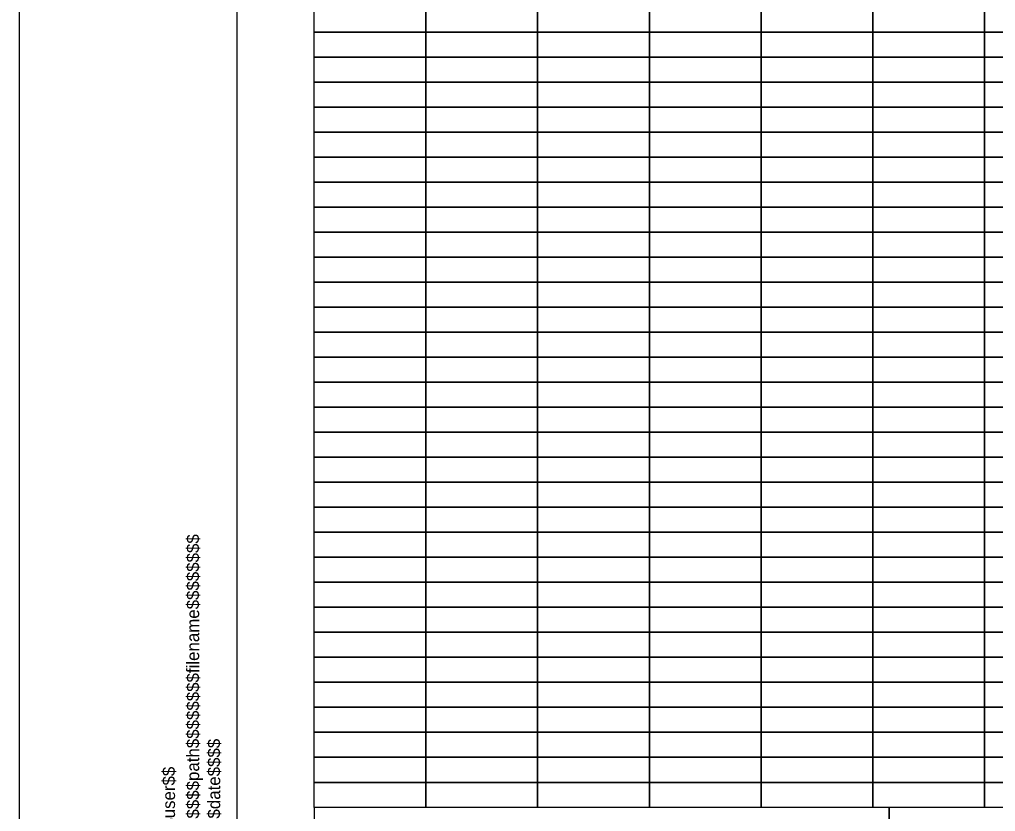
# Model space of a CAD drawing. Extents: x 14330 to 16126, y 15844 to 16994.
# Drawn here: x 14329.7 to 14784.3, y 16045.6 to 16414.6 of the extents above; entities that cross this region are included whole.
import ezdxf

# ---------------------------------------------------------------- set-up
doc = ezdxf.new("R2010")
doc.units = 0
for name, color, linetype in [('RD_SHT_Bndy', 7, 'Continuous'), ('RD_SHT_ID', 7, 'Continuous'), ('RD_SHT_Iplotshp', 7, 'Continuous'), ('RD_SHT_Snap', 7, 'Continuous')]:
    doc.layers.add(name, color=color, linetype=linetype)

msp = doc.modelspace()

# ---------------------------------------------------------------- linework, layer by layer
at = {"layer": 'RD_SHT_Bndy'}
msp.add_line((14430.85, 16943.63), (14430.85, 15893.63), dxfattribs=at)
for points in [[(14518.98, 16408.81), (14466.94, 16408.81), (14466.94, 16420.46), (14518.98, 16420.46)], [(14571.02, 16408.81), (14518.98, 16408.81), (14518.98, 16420.46), (14571.02, 16420.46)], [(14623.07, 16408.81), (14571.02, 16408.81), (14571.02, 16420.46), (14623.07, 16420.46)], [(14675.11, 16408.81), (14623.07, 16408.81), (14623.07, 16420.46), (14675.11, 16420.46)], [(14727.15, 16408.81), (14675.11, 16408.81), (14675.11, 16420.46), (14727.15, 16420.46)], [(14779.19, 16408.81), (14727.15, 16408.81), (14727.15, 16420.46), (14779.19, 16420.46)], [(14831.23, 16408.81), (14779.19, 16408.81), (14779.19, 16420.46), (14831.23, 16420.46)], [(14518.98, 16397.15), (14466.94, 16397.15), (14466.94, 16408.81), (14518.98, 16408.81)], [(14571.02, 16397.15), (14518.98, 16397.15), (14518.98, 16408.81), (14571.02, 16408.81)], [(14623.07, 16397.15), (14571.02, 16397.15), (14571.02, 16408.81), (14623.07, 16408.81)], [(14675.11, 16397.15), (14623.07, 16397.15), (14623.07, 16408.81), (14675.11, 16408.81)], [(14727.15, 16397.15), (14675.11, 16397.15), (14675.11, 16408.81), (14727.15, 16408.81)], [(14779.19, 16397.15), (14727.15, 16397.15), (14727.15, 16408.81), (14779.19, 16408.81)], [(14831.23, 16397.15), (14779.19, 16397.15), (14779.19, 16408.81), (14831.23, 16408.81)], [(14518.98, 16385.5), (14466.94, 16385.5), (14466.94, 16397.15), (14518.98, 16397.15)], [(14571.02, 16385.5), (14518.98, 16385.5), (14518.98, 16397.15), (14571.02, 16397.15)], [(14623.07, 16385.5), (14571.02, 16385.5), (14571.02, 16397.15), (14623.07, 16397.15)], [(14675.11, 16385.5), (14623.07, 16385.5), (14623.07, 16397.15), (14675.11, 16397.15)], [(14727.15, 16385.5), (14675.11, 16385.5), (14675.11, 16397.15), (14727.15, 16397.15)], [(14779.19, 16385.5), (14727.15, 16385.5), (14727.15, 16397.15), (14779.19, 16397.15)], [(14831.23, 16385.5), (14779.19, 16385.5), (14779.19, 16397.15), (14831.23, 16397.15)], [(14518.98, 16373.84), (14466.94, 16373.84), (14466.94, 16385.5), (14518.98, 16385.5)], [(14571.02, 16373.84), (14518.98, 16373.84), (14518.98, 16385.5), (14571.02, 16385.5)], [(14623.07, 16373.84), (14571.02, 16373.84), (14571.02, 16385.5), (14623.07, 16385.5)], [(14675.11, 16373.84), (14623.07, 16373.84), (14623.07, 16385.5), (14675.11, 16385.5)], [(14727.15, 16373.84), (14675.11, 16373.84), (14675.11, 16385.5), (14727.15, 16385.5)], [(14779.19, 16373.84), (14727.15, 16373.84), (14727.15, 16385.5), (14779.19, 16385.5)], [(14831.23, 16373.84), (14779.19, 16373.84), (14779.19, 16385.5), (14831.23, 16385.5)], [(14518.98, 16362.19), (14466.94, 16362.19), (14466.94, 16373.84), (14518.98, 16373.84)], [(14571.02, 16362.19), (14518.98, 16362.19), (14518.98, 16373.84), (14571.02, 16373.84)], [(14623.07, 16362.19), (14571.02, 16362.19), (14571.02, 16373.84), (14623.07, 16373.84)], [(14675.11, 16362.19), (14623.07, 16362.19), (14623.07, 16373.84), (14675.11, 16373.84)], [(14727.15, 16362.19), (14675.11, 16362.19), (14675.11, 16373.84), (14727.15, 16373.84)], [(14779.19, 16362.19), (14727.15, 16362.19), (14727.15, 16373.84), (14779.19, 16373.84)], [(14831.23, 16362.19), (14779.19, 16362.19), (14779.19, 16373.84), (14831.23, 16373.84)], [(14518.98, 16350.53), (14466.94, 16350.53), (14466.94, 16362.19), (14518.98, 16362.19)], [(14571.02, 16350.53), (14518.98, 16350.53), (14518.98, 16362.19), (14571.02, 16362.19)], [(14623.07, 16350.53), (14571.02, 16350.53), (14571.02, 16362.19), (14623.07, 16362.19)], [(14675.11, 16350.53), (14623.07, 16350.53), (14623.07, 16362.19), (14675.11, 16362.19)], [(14727.15, 16350.53), (14675.11, 16350.53), (14675.11, 16362.19), (14727.15, 16362.19)], [(14779.19, 16350.53), (14727.15, 16350.53), (14727.15, 16362.19), (14779.19, 16362.19)], [(14831.23, 16350.53), (14779.19, 16350.53), (14779.19, 16362.19), (14831.23, 16362.19)], [(14518.98, 16338.88), (14466.94, 16338.88), (14466.94, 16350.53), (14518.98, 16350.53)], [(14571.02, 16338.88), (14518.98, 16338.88), (14518.98, 16350.53), (14571.02, 16350.53)], [(14623.07, 16338.88), (14571.02, 16338.88), (14571.02, 16350.53), (14623.07, 16350.53)], [(14675.11, 16338.88), (14623.07, 16338.88), (14623.07, 16350.53), (14675.11, 16350.53)], [(14727.15, 16338.88), (14675.11, 16338.88), (14675.11, 16350.53), (14727.15, 16350.53)], [(14779.19, 16338.88), (14727.15, 16338.88), (14727.15, 16350.53), (14779.19, 16350.53)], [(14831.23, 16338.88), (14779.19, 16338.88), (14779.19, 16350.53), (14831.23, 16350.53)], [(14518.98, 16327.22), (14466.94, 16327.22), (14466.94, 16338.88), (14518.98, 16338.88)], [(14571.02, 16327.22), (14518.98, 16327.22), (14518.98, 16338.88), (14571.02, 16338.88)], [(14623.07, 16327.22), (14571.02, 16327.22), (14571.02, 16338.88), (14623.07, 16338.88)], [(14675.11, 16327.22), (14623.07, 16327.22), (14623.07, 16338.88), (14675.11, 16338.88)], [(14727.15, 16327.22), (14675.11, 16327.22), (14675.11, 16338.88), (14727.15, 16338.88)], [(14779.19, 16327.22), (14727.15, 16327.22), (14727.15, 16338.88), (14779.19, 16338.88)], [(14831.23, 16327.22), (14779.19, 16327.22), (14779.19, 16338.88), (14831.23, 16338.88)], [(14518.98, 16315.57), (14466.94, 16315.57), (14466.94, 16327.22), (14518.98, 16327.22)], [(14571.02, 16315.57), (14518.98, 16315.57), (14518.98, 16327.22), (14571.02, 16327.22)], [(14623.07, 16315.57), (14571.02, 16315.57), (14571.02, 16327.22), (14623.07, 16327.22)], [(14675.11, 16315.57), (14623.07, 16315.57), (14623.07, 16327.22), (14675.11, 16327.22)], [(14727.15, 16315.57), (14675.11, 16315.57), (14675.11, 16327.22), (14727.15, 16327.22)], [(14779.19, 16315.57), (14727.15, 16315.57), (14727.15, 16327.22), (14779.19, 16327.22)], [(14831.23, 16315.57), (14779.19, 16315.57), (14779.19, 16327.22), (14831.23, 16327.22)], [(14518.98, 16303.91), (14466.94, 16303.91), (14466.94, 16315.57), (14518.98, 16315.57)], [(14571.02, 16303.91), (14518.98, 16303.91), (14518.98, 16315.57), (14571.02, 16315.57)], [(14623.07, 16303.91), (14571.02, 16303.91), (14571.02, 16315.57), (14623.07, 16315.57)], [(14675.11, 16303.91), (14623.07, 16303.91), (14623.07, 16315.57), (14675.11, 16315.57)], [(14727.15, 16303.91), (14675.11, 16303.91), (14675.11, 16315.57), (14727.15, 16315.57)], [(14779.19, 16303.91), (14727.15, 16303.91), (14727.15, 16315.57), (14779.19, 16315.57)], [(14831.23, 16303.91), (14779.19, 16303.91), (14779.19, 16315.57), (14831.23, 16315.57)], [(14518.98, 16292.26), (14466.94, 16292.26), (14466.94, 16303.91), (14518.98, 16303.91)], [(14571.02, 16292.26), (14518.98, 16292.26), (14518.98, 16303.91), (14571.02, 16303.91)], [(14623.07, 16292.26), (14571.02, 16292.26), (14571.02, 16303.91), (14623.07, 16303.91)], [(14675.11, 16292.26), (14623.07, 16292.26), (14623.07, 16303.91), (14675.11, 16303.91)], [(14727.15, 16292.26), (14675.11, 16292.26), (14675.11, 16303.91), (14727.15, 16303.91)], [(14779.19, 16292.26), (14727.15, 16292.26), (14727.15, 16303.91), (14779.19, 16303.91)], [(14831.23, 16292.26), (14779.19, 16292.26), (14779.19, 16303.91), (14831.23, 16303.91)], [(14518.98, 16280.6), (14466.94, 16280.6), (14466.94, 16292.26), (14518.98, 16292.26)], [(14571.02, 16280.6), (14518.98, 16280.6), (14518.98, 16292.26), (14571.02, 16292.26)], [(14623.07, 16280.6), (14571.02, 16280.6), (14571.02, 16292.26), (14623.07, 16292.26)], [(14675.11, 16280.6), (14623.07, 16280.6), (14623.07, 16292.26), (14675.11, 16292.26)], [(14727.15, 16280.6), (14675.11, 16280.6), (14675.11, 16292.26), (14727.15, 16292.26)], [(14779.19, 16280.6), (14727.15, 16280.6), (14727.15, 16292.26), (14779.19, 16292.26)], [(14831.23, 16280.6), (14779.19, 16280.6), (14779.19, 16292.26), (14831.23, 16292.26)], [(14518.98, 16268.95), (14466.94, 16268.95), (14466.94, 16280.6), (14518.98, 16280.6)], [(14571.02, 16268.95), (14518.98, 16268.95), (14518.98, 16280.6), (14571.02, 16280.6)], [(14623.07, 16268.95), (14571.02, 16268.95), (14571.02, 16280.6), (14623.07, 16280.6)], [(14675.11, 16268.95), (14623.07, 16268.95), (14623.07, 16280.6), (14675.11, 16280.6)], [(14727.15, 16268.95), (14675.11, 16268.95), (14675.11, 16280.6), (14727.15, 16280.6)], [(14779.19, 16268.95), (14727.15, 16268.95), (14727.15, 16280.6), (14779.19, 16280.6)], [(14831.23, 16268.95), (14779.19, 16268.95), (14779.19, 16280.6), (14831.23, 16280.6)], [(14518.98, 16257.29), (14466.94, 16257.29), (14466.94, 16268.95), (14518.98, 16268.95)], [(14571.02, 16257.29), (14518.98, 16257.29), (14518.98, 16268.95), (14571.02, 16268.95)], [(14623.07, 16257.29), (14571.02, 16257.29), (14571.02, 16268.95), (14623.07, 16268.95)], [(14675.11, 16257.29), (14623.07, 16257.29), (14623.07, 16268.95), (14675.11, 16268.95)], [(14727.15, 16257.29), (14675.11, 16257.29), (14675.11, 16268.95), (14727.15, 16268.95)], [(14779.19, 16257.29), (14727.15, 16257.29), (14727.15, 16268.95), (14779.19, 16268.95)], [(14831.23, 16257.29), (14779.19, 16257.29), (14779.19, 16268.95), (14831.23, 16268.95)], [(14518.98, 16245.64), (14466.94, 16245.64), (14466.94, 16257.29), (14518.98, 16257.29)], [(14571.02, 16245.64), (14518.98, 16245.64), (14518.98, 16257.29), (14571.02, 16257.29)], [(14623.07, 16245.64), (14571.02, 16245.64), (14571.02, 16257.29), (14623.07, 16257.29)], [(14675.11, 16245.64), (14623.07, 16245.64), (14623.07, 16257.29), (14675.11, 16257.29)], [(14727.15, 16245.64), (14675.11, 16245.64), (14675.11, 16257.29), (14727.15, 16257.29)], [(14779.19, 16245.64), (14727.15, 16245.64), (14727.15, 16257.29), (14779.19, 16257.29)], [(14831.23, 16245.64), (14779.19, 16245.64), (14779.19, 16257.29), (14831.23, 16257.29)], [(14518.98, 16233.98), (14466.94, 16233.98), (14466.94, 16245.64), (14518.98, 16245.64)], [(14571.02, 16233.98), (14518.98, 16233.98), (14518.98, 16245.64), (14571.02, 16245.64)], [(14623.07, 16233.98), (14571.02, 16233.98), (14571.02, 16245.64), (14623.07, 16245.64)], [(14675.11, 16233.98), (14623.07, 16233.98), (14623.07, 16245.64), (14675.11, 16245.64)], [(14727.15, 16233.98), (14675.11, 16233.98), (14675.11, 16245.64), (14727.15, 16245.64)], [(14779.19, 16233.98), (14727.15, 16233.98), (14727.15, 16245.64), (14779.19, 16245.64)], [(14831.23, 16233.98), (14779.19, 16233.98), (14779.19, 16245.64), (14831.23, 16245.64)], [(14518.98, 16222.33), (14466.94, 16222.33), (14466.94, 16233.98), (14518.98, 16233.98)], [(14571.02, 16222.33), (14518.98, 16222.33), (14518.98, 16233.98), (14571.02, 16233.98)], [(14623.07, 16222.33), (14571.02, 16222.33), (14571.02, 16233.98), (14623.07, 16233.98)], [(14675.11, 16222.33), (14623.07, 16222.33), (14623.07, 16233.98), (14675.11, 16233.98)], [(14727.15, 16222.33), (14675.11, 16222.33), (14675.11, 16233.98), (14727.15, 16233.98)], [(14779.19, 16222.33), (14727.15, 16222.33), (14727.15, 16233.98), (14779.19, 16233.98)], [(14831.23, 16222.33), (14779.19, 16222.33), (14779.19, 16233.98), (14831.23, 16233.98)], [(14518.98, 16210.67), (14466.94, 16210.67), (14466.94, 16222.33), (14518.98, 16222.33)], [(14571.02, 16210.67), (14518.98, 16210.67), (14518.98, 16222.33), (14571.02, 16222.33)], [(14623.07, 16210.67), (14571.02, 16210.67), (14571.02, 16222.33), (14623.07, 16222.33)], [(14675.11, 16210.67), (14623.07, 16210.67), (14623.07, 16222.33), (14675.11, 16222.33)], [(14727.15, 16210.67), (14675.11, 16210.67), (14675.11, 16222.33), (14727.15, 16222.33)], [(14779.19, 16210.67), (14727.15, 16210.67), (14727.15, 16222.33), (14779.19, 16222.33)], [(14831.23, 16210.67), (14779.19, 16210.67), (14779.19, 16222.33), (14831.23, 16222.33)], [(14518.98, 16199.02), (14466.94, 16199.02), (14466.94, 16210.67), (14518.98, 16210.67)], [(14571.02, 16199.02), (14518.98, 16199.02), (14518.98, 16210.67), (14571.02, 16210.67)], [(14623.07, 16199.02), (14571.02, 16199.02), (14571.02, 16210.67), (14623.07, 16210.67)], [(14675.11, 16199.02), (14623.07, 16199.02), (14623.07, 16210.67), (14675.11, 16210.67)], [(14727.15, 16199.02), (14675.11, 16199.02), (14675.11, 16210.67), (14727.15, 16210.67)], [(14779.19, 16199.02), (14727.15, 16199.02), (14727.15, 16210.67), (14779.19, 16210.67)], [(14831.23, 16199.02), (14779.19, 16199.02), (14779.19, 16210.67), (14831.23, 16210.67)], [(14518.98, 16187.36), (14466.94, 16187.36), (14466.94, 16199.02), (14518.98, 16199.02)], [(14571.02, 16187.36), (14518.98, 16187.36), (14518.98, 16199.02), (14571.02, 16199.02)], [(14623.07, 16187.36), (14571.02, 16187.36), (14571.02, 16199.02), (14623.07, 16199.02)], [(14675.11, 16187.36), (14623.07, 16187.36), (14623.07, 16199.02), (14675.11, 16199.02)], [(14727.15, 16187.36), (14675.11, 16187.36), (14675.11, 16199.02), (14727.15, 16199.02)], [(14779.19, 16187.36), (14727.15, 16187.36), (14727.15, 16199.02), (14779.19, 16199.02)], [(14831.23, 16187.36), (14779.19, 16187.36), (14779.19, 16199.02), (14831.23, 16199.02)], [(14518.98, 16175.71), (14466.94, 16175.71), (14466.94, 16187.36), (14518.98, 16187.36)], [(14571.02, 16175.71), (14518.98, 16175.71), (14518.98, 16187.36), (14571.02, 16187.36)], [(14623.07, 16175.71), (14571.02, 16175.71), (14571.02, 16187.36), (14623.07, 16187.36)], [(14675.11, 16175.71), (14623.07, 16175.71), (14623.07, 16187.36), (14675.11, 16187.36)], [(14727.15, 16175.71), (14675.11, 16175.71), (14675.11, 16187.36), (14727.15, 16187.36)], [(14779.19, 16175.71), (14727.15, 16175.71), (14727.15, 16187.36), (14779.19, 16187.36)], [(14831.23, 16175.71), (14779.19, 16175.71), (14779.19, 16187.36), (14831.23, 16187.36)], [(14518.98, 16164.05), (14466.94, 16164.05), (14466.94, 16175.71), (14518.98, 16175.71)], [(14571.02, 16164.05), (14518.98, 16164.05), (14518.98, 16175.71), (14571.02, 16175.71)], [(14623.07, 16164.05), (14571.02, 16164.05), (14571.02, 16175.71), (14623.07, 16175.71)], [(14675.11, 16164.05), (14623.07, 16164.05), (14623.07, 16175.71), (14675.11, 16175.71)], [(14727.15, 16164.05), (14675.11, 16164.05), (14675.11, 16175.71), (14727.15, 16175.71)], [(14779.19, 16164.05), (14727.15, 16164.05), (14727.15, 16175.71), (14779.19, 16175.71)], [(14831.23, 16164.05), (14779.19, 16164.05), (14779.19, 16175.71), (14831.23, 16175.71)], [(14518.98, 16152.39), (14466.94, 16152.39), (14466.94, 16164.05), (14518.98, 16164.05)], [(14571.02, 16152.39), (14518.98, 16152.39), (14518.98, 16164.05), (14571.02, 16164.05)], [(14623.07, 16152.39), (14571.02, 16152.39), (14571.02, 16164.05), (14623.07, 16164.05)], [(14675.11, 16152.39), (14623.07, 16152.39), (14623.07, 16164.05), (14675.11, 16164.05)], [(14727.15, 16152.39), (14675.11, 16152.39), (14675.11, 16164.05), (14727.15, 16164.05)], [(14779.19, 16152.39), (14727.15, 16152.39), (14727.15, 16164.05), (14779.19, 16164.05)], [(14831.23, 16152.39), (14779.19, 16152.39), (14779.19, 16164.05), (14831.23, 16164.05)], [(14518.98, 16140.74), (14466.94, 16140.74), (14466.94, 16152.39), (14518.98, 16152.39)], [(14571.02, 16140.74), (14518.98, 16140.74), (14518.98, 16152.39), (14571.02, 16152.39)], [(14623.07, 16140.74), (14571.02, 16140.74), (14571.02, 16152.39), (14623.07, 16152.39)], [(14675.11, 16140.74), (14623.07, 16140.74), (14623.07, 16152.39), (14675.11, 16152.39)], [(14727.15, 16140.74), (14675.11, 16140.74), (14675.11, 16152.39), (14727.15, 16152.39)], [(14779.19, 16140.74), (14727.15, 16140.74), (14727.15, 16152.39), (14779.19, 16152.39)], [(14831.23, 16140.74), (14779.19, 16140.74), (14779.19, 16152.39), (14831.23, 16152.39)], [(14518.98, 16129.08), (14466.94, 16129.08), (14466.94, 16140.74), (14518.98, 16140.74)], [(14571.02, 16129.08), (14518.98, 16129.08), (14518.98, 16140.74), (14571.02, 16140.74)], [(14623.07, 16129.08), (14571.02, 16129.08), (14571.02, 16140.74), (14623.07, 16140.74)], [(14675.11, 16129.08), (14623.07, 16129.08), (14623.07, 16140.74), (14675.11, 16140.74)], [(14727.15, 16129.08), (14675.11, 16129.08), (14675.11, 16140.74), (14727.15, 16140.74)], [(14779.19, 16129.08), (14727.15, 16129.08), (14727.15, 16140.74), (14779.19, 16140.74)], [(14831.23, 16129.08), (14779.19, 16129.08), (14779.19, 16140.74), (14831.23, 16140.74)], [(14518.98, 16117.43), (14466.94, 16117.43), (14466.94, 16129.08), (14518.98, 16129.08)], [(14571.02, 16117.43), (14518.98, 16117.43), (14518.98, 16129.08), (14571.02, 16129.08)], [(14623.07, 16117.43), (14571.02, 16117.43), (14571.02, 16129.08), (14623.07, 16129.08)], [(14675.11, 16117.43), (14623.07, 16117.43), (14623.07, 16129.08), (14675.11, 16129.08)], [(14727.15, 16117.43), (14675.11, 16117.43), (14675.11, 16129.08), (14727.15, 16129.08)], [(14779.19, 16117.43), (14727.15, 16117.43), (14727.15, 16129.08), (14779.19, 16129.08)], [(14831.23, 16117.43), (14779.19, 16117.43), (14779.19, 16129.08), (14831.23, 16129.08)], [(14518.98, 16105.77), (14466.94, 16105.77), (14466.94, 16117.43), (14518.98, 16117.43)], [(14571.02, 16105.77), (14518.98, 16105.77), (14518.98, 16117.43), (14571.02, 16117.43)], [(14623.07, 16105.77), (14571.02, 16105.77), (14571.02, 16117.43), (14623.07, 16117.43)], [(14675.11, 16105.77), (14623.07, 16105.77), (14623.07, 16117.43), (14675.11, 16117.43)], [(14727.15, 16105.77), (14675.11, 16105.77), (14675.11, 16117.43), (14727.15, 16117.43)], [(14779.19, 16105.77), (14727.15, 16105.77), (14727.15, 16117.43), (14779.19, 16117.43)], [(14831.23, 16105.77), (14779.19, 16105.77), (14779.19, 16117.43), (14831.23, 16117.43)], [(14518.98, 16094.12), (14466.94, 16094.12), (14466.94, 16105.77), (14518.98, 16105.77)], [(14571.02, 16094.12), (14518.98, 16094.12), (14518.98, 16105.77), (14571.02, 16105.77)], [(14623.07, 16094.12), (14571.02, 16094.12), (14571.02, 16105.77), (14623.07, 16105.77)], [(14675.11, 16094.12), (14623.07, 16094.12), (14623.07, 16105.77), (14675.11, 16105.77)], [(14727.15, 16094.12), (14675.11, 16094.12), (14675.11, 16105.77), (14727.15, 16105.77)], [(14779.19, 16094.12), (14727.15, 16094.12), (14727.15, 16105.77), (14779.19, 16105.77)], [(14831.23, 16094.12), (14779.19, 16094.12), (14779.19, 16105.77), (14831.23, 16105.77)], [(14518.98, 16082.46), (14466.94, 16082.46), (14466.94, 16094.12), (14518.98, 16094.12)], [(14571.02, 16082.46), (14518.98, 16082.46), (14518.98, 16094.12), (14571.02, 16094.12)], [(14623.07, 16082.46), (14571.02, 16082.46), (14571.02, 16094.12), (14623.07, 16094.12)], [(14675.11, 16082.46), (14623.07, 16082.46), (14623.07, 16094.12), (14675.11, 16094.12)], [(14727.15, 16082.46), (14675.11, 16082.46), (14675.11, 16094.12), (14727.15, 16094.12)], [(14779.19, 16082.46), (14727.15, 16082.46), (14727.15, 16094.12), (14779.19, 16094.12)], [(14831.23, 16082.46), (14779.19, 16082.46), (14779.19, 16094.12), (14831.23, 16094.12)], [(14518.98, 16070.81), (14466.94, 16070.81), (14466.94, 16082.46), (14518.98, 16082.46)], [(14571.02, 16070.81), (14518.98, 16070.81), (14518.98, 16082.46), (14571.02, 16082.46)], [(14623.07, 16070.81), (14571.02, 16070.81), (14571.02, 16082.46), (14623.07, 16082.46)], [(14675.11, 16070.81), (14623.07, 16070.81), (14623.07, 16082.46), (14675.11, 16082.46)], [(14727.15, 16070.81), (14675.11, 16070.81), (14675.11, 16082.46), (14727.15, 16082.46)], [(14779.19, 16070.81), (14727.15, 16070.81), (14727.15, 16082.46), (14779.19, 16082.46)], [(14831.23, 16070.81), (14779.19, 16070.81), (14779.19, 16082.46), (14831.23, 16082.46)], [(14518.98, 16059.15), (14466.94, 16059.15), (14466.94, 16070.81), (14518.98, 16070.81)], [(14571.02, 16059.15), (14518.98, 16059.15), (14518.98, 16070.81), (14571.02, 16070.81)], [(14623.07, 16059.15), (14571.02, 16059.15), (14571.02, 16070.81), (14623.07, 16070.81)], [(14675.11, 16059.15), (14623.07, 16059.15), (14623.07, 16070.81), (14675.11, 16070.81)], [(14727.15, 16059.15), (14675.11, 16059.15), (14675.11, 16070.81), (14727.15, 16070.81)], [(14779.19, 16059.15), (14727.15, 16059.15), (14727.15, 16070.81), (14779.19, 16070.81)], [(14831.23, 16059.15), (14779.19, 16059.15), (14779.19, 16070.81), (14831.23, 16070.81)], [(14518.98, 16047.5), (14466.94, 16047.5), (14466.94, 16059.15), (14518.98, 16059.15)], [(14571.02, 16047.5), (14518.98, 16047.5), (14518.98, 16059.15), (14571.02, 16059.15)], [(14623.07, 16047.5), (14571.02, 16047.5), (14571.02, 16059.15), (14623.07, 16059.15)], [(14675.11, 16047.5), (14623.07, 16047.5), (14623.07, 16059.15), (14675.11, 16059.15)], [(14727.15, 16047.5), (14675.11, 16047.5), (14675.11, 16059.15), (14727.15, 16059.15)], [(14779.19, 16047.5), (14727.15, 16047.5), (14727.15, 16059.15), (14779.19, 16059.15)], [(14831.23, 16047.5), (14779.19, 16047.5), (14779.19, 16059.15), (14831.23, 16059.15)], [(14466.94, 16032.5), (14734.84, 16032.5), (14734.84, 16047.5), (14466.94, 16047.5)], [(14734.84, 16032.5), (15002.74, 16032.5), (15002.74, 16047.5), (14734.84, 16047.5)]]:
    msp.add_lwpolyline(points, close=True, dxfattribs=at)
at = {"layer": 'RD_SHT_Iplotshp'}
msp.add_lwpolyline([(14329.65, 16968.63), (16125.65, 16968.63), (16125.65, 15868.63), (14329.65, 15868.63)], close=True, dxfattribs=at)
at = {"layer": 'RD_SHT_Snap'}
msp.add_line((14329.65, 15868.63), (14329.65, 16968.63), dxfattribs=at)

# ---------------------------------------------------------------- texts
at = {"layer": 'RD_SHT_ID'}
for s, p in [('$$$$$$path$$$$$$$$filename$$$$$$$$', (14413.35, 16033.53)), ('$$$date$$$$', (14423.15, 16033.53)), ('$$user$$', (14402.1, 16033.63))]:
    msp.add_text(s, height=5.88, rotation=90, dxfattribs=at).set_placement(p)

doc.saveas('drawing.dxf')
